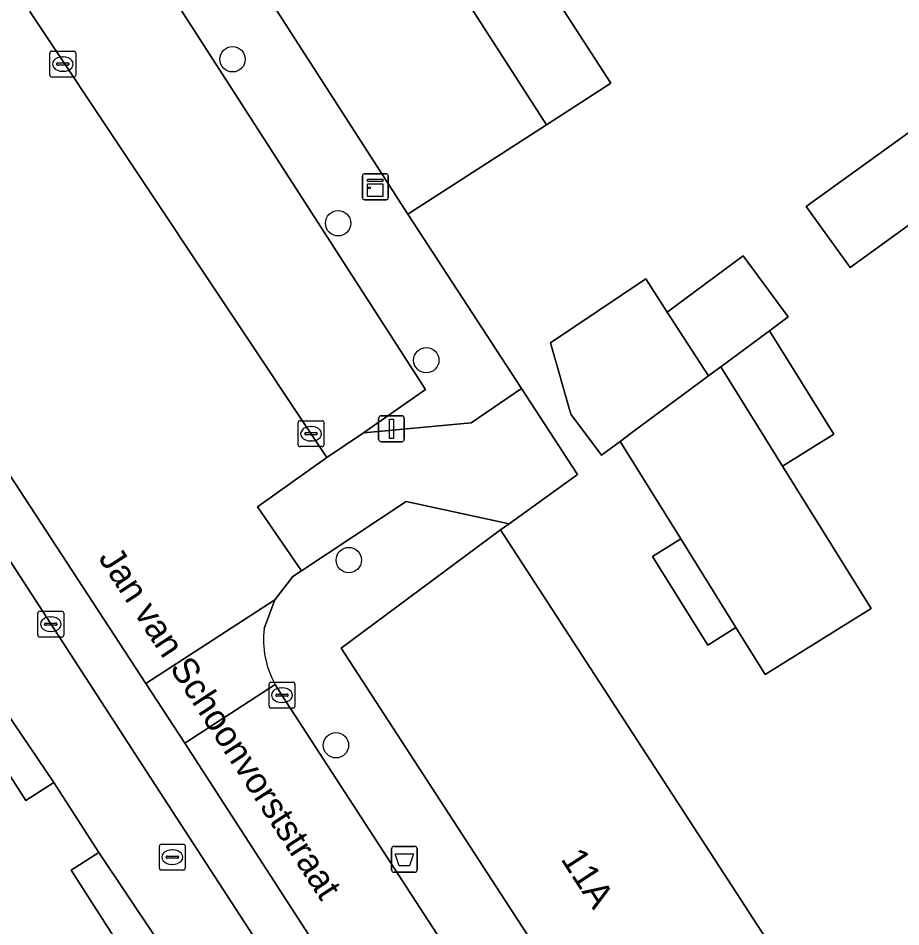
# Model space of a CAD drawing. Extents: x 161798 to 162385, y 382315 to 382833.
# Drawn here: x 161908.41 to 161942.5, y 382533.23 to 382568.31 of the extents above; entities that cross this region are included whole.
import ezdxf

# ---------------------------------------------------------------- set-up
doc = ezdxf.new("R2010")
doc.units = 0
for name, color, linetype in [('IMGEO_Afvalbak', 7, 'Continuous'), ('IMGEO_Boom', 7, 'Continuous'), ('IMGEO_Brandkraan', 7, 'Continuous'), ('IMGEO_Erf', 7, 'Continuous'), ('IMGEO_Kast', 7, 'Continuous'), ('IMGEO_Kolk', 7, 'Continuous'), ('IMGEO_Lichtmast', 7, 'Continuous'), ('IMGEO_Muur', 7, 'Continuous'), ('IMGEO_Openbare_ruimte_label', 7, 'Continuous'), ('IMGEO_Pand', 7, 'Continuous'), ('IMGEO_Pand_nummerreeks', 7, 'Continuous'), ('IMGEO_Parkeervlak_open', 7, 'Continuous'), ('IMGEO_Rijbaan_lokaal_open', 7, 'Continuous'), ('IMGEO_Voetpad_open', 7, 'Continuous')]:
    doc.layers.add(name, color=color, linetype=linetype)

msp = doc.modelspace()

# ---------------------------------------------------------------- linework, layer by layer
at = {"layer": 'IMGEO_Afvalbak'}
for p, q in [((161922.83, 382535.436), (161922.83, 382536.236)), ((161922.83, 382536.236), (161922.83, 382535.436)), ((161922.93, 382536.336), (161923.72, 382536.336)), ((161923.72, 382536.336), (161922.93, 382536.336)), ((161923.82, 382536.236), (161923.82, 382535.436)), ((161923.82, 382535.436), (161923.82, 382536.236)), ((161923.72, 382535.336), (161922.93, 382535.336)), ((161922.93, 382535.336), (161923.72, 382535.336))]:
    msp.add_line(p, q, dxfattribs=at)
msp.add_lwpolyline([(161922.973, 382536.05), (161923.677, 382536.05), (161923.528, 382535.58), (161923.122, 382535.58), (161922.973, 382536.05)], dxfattribs=at)
for centre, start, end in [((161922.93, 382536.236), 90, 180), ((161922.93, 382536.236), 90, 180), ((161923.72, 382536.236), 0, 90), ((161923.72, 382536.236), 360, 90), ((161922.93, 382535.436), 180, 270), ((161922.93, 382535.436), 180, 270), ((161923.72, 382535.436), 270, 0), ((161923.72, 382535.436), 270, 0)]:
    msp.add_arc(centre, 0.1, start, end, dxfattribs=at)
at = {"layer": 'IMGEO_Boom'}
for centre in [(161916.691, 382566.72), (161920.768, 382560.39), (161924.174, 382555.102), (161921.179, 382547.388), (161920.685, 382540.238)]:
    msp.add_circle(centre, 0.489, dxfattribs=at)
at = {"layer": 'IMGEO_Brandkraan'}
for p, q in [((161913.866, 382535.494), (161913.866, 382536.346)), ((161913.941, 382536.42), (161914.793, 382536.42)), ((161914.354, 382536.2), (161914.379, 382536.2)), ((161914.867, 382536.346), (161914.867, 382535.494)), ((161914.125, 382535.914), (161914.125, 382535.926)), ((161914.563, 382535.877), (161914.165, 382535.877)), ((161914.168, 382535.963), (161914.566, 382535.963)), ((161914.609, 382535.926), (161914.609, 382535.914)), ((161914.793, 382535.42), (161913.941, 382535.42)), ((161914.377, 382535.64), (161914.352, 382535.64))]:
    msp.add_line(p, q, dxfattribs=at)
for points in [[(161913.866, 382535.494), (161913.866, 382536.346)], [(161913.941, 382536.42), (161914.793, 382536.42)], [(161914.867, 382536.346), (161914.867, 382535.494)], [(161914.793, 382535.42), (161913.941, 382535.42)]]:
    msp.add_lwpolyline(points, dxfattribs=at)
for centre, radius, start, end in [((161913.943, 382536.344), 0.0765, 91.552, 178.448), ((161913.943, 382536.344), 0.0765, 91.552, 178.448), ((161914.791, 382536.344), 0.0765, 1.552, 88.448), ((161914.791, 382536.344), 0.0765, 1.552, 88.448), ((161914.165, 382535.923), 0.0403, 85.8775, 175.7526), ((161914.162, 382535.913), 0.0366, 178.938, 274.7102), ((161914.566, 382535.92), 0.043, 264.8664, 352.4533), ((161914.57, 382535.925), 0.0386, 1.7309, 96.639), ((161913.943, 382535.496), 0.0765, 181.552, 268.448), ((161913.943, 382535.496), 0.0765, 181.552, 268.448), ((161914.791, 382535.496), 0.0765, 271.552, 358.448), ((161914.791, 382535.496), 0.0765, 271.552, 358.448)]:
    msp.add_arc(centre, radius, start, end, dxfattribs=at)
for centre, major_axis, ratio, start_param, end_param in [((161914.353, 382535.92), (-0.387, 0.002), 0.722429, 4.712389, 7.853982), ((161914.378, 382535.92), (-0.39, 0.002), 0.717154, 1.570796, 4.712389)]:
    msp.add_ellipse(centre, major_axis=major_axis, ratio=ratio, start_param=start_param, end_param=end_param, dxfattribs=at)
at = {"layer": 'IMGEO_Erf'}
for points in [[(161945.057, 382574.729), (161940.162, 382571.576), (161937.799, 382570.027), (161937.504, 382569.837), (161935.277, 382573.295), (161932.843, 382571.727), (161929.049, 382569.284), (161931.298, 382565.792), (161928.82, 382564.196), (161923.464, 382560.747), (161927.849, 382554.013), (161930.015, 382550.687), (161927.378, 382548.793), (161927.045, 382548.554), (161941.278, 382526.66), (161942.03, 382525.503), (161945.338, 382527.569)], [(161889.755, 382530.763), (161886.621, 382535.643), (161887.378, 382536.128), (161899.179, 382543.71), (161903.381, 382546.409), (161908.71, 382538.113), (161909.788, 382538.805), (161900.489, 382552.547), (161897.075, 382557.59), (161893.716, 382555.371), (161890.552, 382560.159), (161883.925, 382555.781)], [(161924.608, 382516.565), (161911.526, 382536.099), (161910.458, 382535.413), (161915.897, 382526.946)]]:
    msp.add_lwpolyline(points, dxfattribs=at)
for points in [[(161945.946, 382562.594), (161940.543, 382558.688), (161938.848, 382561.033), (161944.377, 382565.031), (161949.608, 382568.813), (161951.303, 382566.468)], [(161941.353, 382545.523), (161937.26, 382542.972), (161936.132, 382544.781), (161935.046, 382544.104), (161932.91, 382547.532), (161933.996, 382548.209), (161931.654, 382551.965), (161930.934, 382551.433), (161929.755, 382553.026), (161928.969, 382555.771), (161932.652, 382558.246), (161933.478, 382556.963), (161936.408, 382559.133), (161938.152, 382556.779), (161937.423, 382556.239), (161939.908, 382552.253), (161937.928, 382551.018)]]:
    msp.add_lwpolyline(points, close=True, dxfattribs=at)
at = {"layer": 'IMGEO_Kast'}
for p, q in [((161921.706, 382561.372), (161921.706, 382562.213)), ((161921.706, 382562.213), (161921.706, 382561.372)), ((161921.781, 382562.297), (161922.622, 382562.297)), ((161922.622, 382562.297), (161921.781, 382562.297)), ((161922.706, 382562.222), (161922.706, 382561.381)), ((161922.706, 382561.381), (161922.706, 382562.222)), ((161922.631, 382561.297), (161921.79, 382561.297)), ((161921.79, 382561.297), (161922.631, 382561.297))]:
    msp.add_line(p, q, dxfattribs=at)
for points in [[(161921.901, 382562.087), (161922.501, 382562.087), (161922.501, 382562.002), (161921.901, 382562.002), (161921.901, 382562.087)], [(161921.901, 382561.912), (161922.501, 382561.912), (161922.501, 382561.423), (161921.901, 382561.423), (161921.901, 382561.912)]]:
    msp.add_lwpolyline(points, dxfattribs=at)
msp.add_circle((161921.985, 382561.761), 0.0377, dxfattribs=at)
for centre, start, end in [((161921.784, 382562.219), 92.4484, 184.2845), ((161921.784, 382562.219), 92.4484, 184.2845), ((161922.628, 382562.219), 2.4484, 94.2845), ((161922.628, 382562.219), 2.4484, 94.2845), ((161921.784, 382561.375), 182.4484, 274.2845), ((161921.784, 382561.375), 182.4484, 274.2845), ((161922.628, 382561.375), 272.4484, 4.2845), ((161922.628, 382561.375), 272.4484, 4.2845)]:
    msp.add_arc(centre, 0.0779, start, end, dxfattribs=at)
at = {"layer": 'IMGEO_Kolk'}
for p, q in [((161909.634, 382566.11), (161909.634, 382566.962)), ((161909.709, 382567.036), (161910.561, 382567.036)), ((161910.635, 382566.962), (161910.635, 382566.11)), ((161910.122, 382566.816), (161910.147, 382566.816)), ((161909.893, 382566.53), (161909.893, 382566.542)), ((161910.331, 382566.493), (161909.933, 382566.493)), ((161909.936, 382566.579), (161910.334, 382566.579)), ((161910.145, 382566.256), (161910.12, 382566.256)), ((161910.377, 382566.542), (161910.377, 382566.53)), ((161910.561, 382566.036), (161909.709, 382566.036)), ((161919.222, 382551.84), (161919.222, 382552.692)), ((161919.297, 382552.766), (161920.149, 382552.766)), ((161920.223, 382552.692), (161920.223, 382551.84)), ((161919.481, 382552.26), (161919.481, 382552.272)), ((161919.524, 382552.309), (161919.922, 382552.309)), ((161919.71, 382552.546), (161919.735, 382552.546)), ((161919.965, 382552.272), (161919.965, 382552.26)), ((161919.919, 382552.223), (161919.521, 382552.223)), ((161919.733, 382551.986), (161919.708, 382551.986)), ((161920.149, 382551.766), (161919.297, 382551.766)), ((161909.171, 382544.487), (161909.171, 382545.339)), ((161909.246, 382545.413), (161910.098, 382545.413)), ((161910.172, 382545.339), (161910.172, 382544.487)), ((161909.43, 382544.907), (161909.43, 382544.919)), ((161909.868, 382544.87), (161909.47, 382544.87)), ((161909.473, 382544.956), (161909.871, 382544.956)), ((161909.659, 382545.193), (161909.684, 382545.193)), ((161909.914, 382544.919), (161909.914, 382544.907)), ((161909.682, 382544.633), (161909.657, 382544.633)), ((161910.098, 382544.413), (161909.246, 382544.413)), ((161918.101, 382541.747), (161918.101, 382542.599)), ((161918.176, 382542.673), (161919.028, 382542.673)), ((161918.589, 382542.453), (161918.614, 382542.453)), ((161919.102, 382542.599), (161919.102, 382541.747)), ((161918.36, 382542.167), (161918.36, 382542.179)), ((161918.798, 382542.13), (161918.4, 382542.13)), ((161918.403, 382542.216), (161918.801, 382542.216)), ((161918.844, 382542.179), (161918.844, 382542.167)), ((161918.612, 382541.893), (161918.587, 382541.893)), ((161919.028, 382541.673), (161918.176, 382541.673))]:
    msp.add_line(p, q, dxfattribs=at)
for points in [[(161909.634, 382566.11), (161909.634, 382566.962)], [(161909.709, 382567.036), (161910.561, 382567.036)], [(161910.635, 382566.962), (161910.635, 382566.11)], [(161910.561, 382566.036), (161909.709, 382566.036)], [(161919.222, 382551.84), (161919.222, 382552.692)], [(161919.297, 382552.766), (161920.149, 382552.766)], [(161920.223, 382552.692), (161920.223, 382551.84)], [(161920.149, 382551.766), (161919.297, 382551.766)], [(161909.171, 382544.487), (161909.171, 382545.339)], [(161909.246, 382545.413), (161910.098, 382545.413)], [(161910.172, 382545.339), (161910.172, 382544.487)], [(161910.098, 382544.413), (161909.246, 382544.413)], [(161918.101, 382541.747), (161918.101, 382542.599)], [(161918.176, 382542.673), (161919.028, 382542.673)], [(161919.102, 382542.599), (161919.102, 382541.747)], [(161919.028, 382541.673), (161918.176, 382541.673)]]:
    msp.add_lwpolyline(points, dxfattribs=at)
for centre, radius, start, end in [((161909.711, 382566.96), 0.0765, 91.552, 178.448), ((161909.711, 382566.96), 0.0765, 91.552, 178.448), ((161910.559, 382566.96), 0.0765, 1.552, 88.448), ((161910.559, 382566.96), 0.0765, 1.552, 88.448), ((161909.933, 382566.539), 0.0403, 85.8775, 175.7526), ((161909.93, 382566.529), 0.0366, 178.938, 274.7102), ((161910.334, 382566.536), 0.043, 264.8664, 352.4533), ((161910.338, 382566.541), 0.0386, 1.7309, 96.639), ((161909.711, 382566.112), 0.0765, 181.552, 268.448), ((161909.711, 382566.112), 0.0765, 181.552, 268.448), ((161910.559, 382566.112), 0.0765, 271.552, 358.448), ((161910.559, 382566.112), 0.0765, 271.552, 358.448), ((161919.299, 382552.69), 0.0765, 91.552, 178.448), ((161919.299, 382552.69), 0.0765, 91.552, 178.448), ((161920.147, 382552.69), 0.0765, 1.552, 88.448), ((161920.147, 382552.69), 0.0765, 1.552, 88.448), ((161919.521, 382552.269), 0.0403, 85.8775, 175.7526), ((161919.518, 382552.259), 0.0366, 178.938, 274.7102), ((161919.922, 382552.266), 0.043, 264.8664, 352.4533), ((161919.926, 382552.271), 0.0386, 1.7309, 96.639), ((161919.299, 382551.842), 0.0765, 181.552, 268.448), ((161919.299, 382551.842), 0.0765, 181.552, 268.448), ((161920.147, 382551.842), 0.0765, 271.552, 358.448), ((161920.147, 382551.842), 0.0765, 271.552, 358.448), ((161909.248, 382545.337), 0.0765, 91.552, 178.448), ((161909.248, 382545.337), 0.0765, 91.552, 178.448), ((161910.096, 382545.337), 0.0765, 1.552, 88.448), ((161910.096, 382545.337), 0.0765, 1.552, 88.448), ((161909.47, 382544.916), 0.0403, 85.8775, 175.7526), ((161909.467, 382544.906), 0.0366, 178.938, 274.7102), ((161909.871, 382544.913), 0.043, 264.8664, 352.4533), ((161909.875, 382544.918), 0.0386, 1.7309, 96.639), ((161909.248, 382544.489), 0.0765, 181.552, 268.448), ((161909.248, 382544.489), 0.0765, 181.552, 268.448), ((161910.096, 382544.489), 0.0765, 271.552, 358.448), ((161910.096, 382544.489), 0.0765, 271.552, 358.448), ((161918.178, 382542.597), 0.0765, 91.552, 178.448), ((161918.178, 382542.597), 0.0765, 91.552, 178.448), ((161919.026, 382542.597), 0.0765, 1.552, 88.448), ((161919.026, 382542.597), 0.0765, 1.552, 88.448), ((161918.4, 382542.176), 0.0403, 85.8775, 175.7526), ((161918.397, 382542.166), 0.0366, 178.938, 274.7102), ((161918.801, 382542.173), 0.043, 264.8664, 352.4533), ((161918.805, 382542.178), 0.0386, 1.7309, 96.639), ((161918.178, 382541.749), 0.0765, 181.552, 268.448), ((161918.178, 382541.749), 0.0765, 181.552, 268.448), ((161919.026, 382541.749), 0.0765, 271.552, 358.448), ((161919.026, 382541.749), 0.0765, 271.552, 358.448)]:
    msp.add_arc(centre, radius, start, end, dxfattribs=at)
for centre, major_axis, ratio, start_param, end_param in [((161910.121, 382566.536), (-0.387, 0.002), 0.722429, 4.712389, 7.853982), ((161910.146, 382566.536), (-0.39, 0.002), 0.717154, 1.570796, 4.712389), ((161919.709, 382552.266), (-0.387, 0.002), 0.722429, 4.712389, 7.853982), ((161919.734, 382552.266), (-0.39, 0.002), 0.717154, 1.570796, 4.712389), ((161909.658, 382544.913), (-0.387, 0.002), 0.722429, 4.712389, 7.853982), ((161909.683, 382544.913), (-0.39, 0.002), 0.717154, 1.570796, 4.712389), ((161918.588, 382542.173), (-0.387, 0.002), 0.722429, 4.712389, 7.853982), ((161918.613, 382542.173), (-0.39, 0.002), 0.717154, 1.570796, 4.712389)]:
    msp.add_ellipse(centre, major_axis=major_axis, ratio=ratio, start_param=start_param, end_param=end_param, dxfattribs=at)
at = {"layer": 'IMGEO_Lichtmast'}
for p, q in [((161922.433, 382552.958), (161923.223, 382552.958)), ((161923.223, 382552.958), (161922.433, 382552.958)), ((161922.333, 382552.058), (161922.333, 382552.858)), ((161922.333, 382552.858), (161922.333, 382552.058)), ((161923.323, 382552.858), (161923.323, 382552.058)), ((161923.323, 382552.058), (161923.323, 382552.858)), ((161923.223, 382551.958), (161922.433, 382551.958)), ((161922.433, 382551.958), (161923.223, 382551.958))]:
    msp.add_line(p, q, dxfattribs=at)
msp.add_lwpolyline([(161922.753, 382552.833), (161922.903, 382552.833), (161922.903, 382552.083), (161922.753, 382552.083), (161922.753, 382552.833)], dxfattribs=at)
for centre, start, end in [((161922.433, 382552.858), 90, 180), ((161922.433, 382552.858), 90, 180), ((161923.223, 382552.858), 0, 90), ((161923.223, 382552.858), 360, 90), ((161922.433, 382552.058), 180, 270), ((161922.433, 382552.058), 180, 270), ((161923.223, 382552.058), 270, 0), ((161923.223, 382552.058), 270, 0)]:
    msp.add_arc(centre, 0.1, start, end, dxfattribs=at)
at = {"layer": 'IMGEO_Muur'}
for points in [[(161923.464, 382560.747), (161927.849, 382554.013)], [(161927.849, 382554.013), (161930.015, 382550.687)]]:
    msp.add_lwpolyline(points, dxfattribs=at)
at = {"layer": 'IMGEO_Pand'}
for points in [[(161928.82, 382564.196), (161931.298, 382565.792), (161929.049, 382569.284), (161932.843, 382571.727), (161928.086, 382579.115), (161921.815, 382575.076)], [(161928.82, 382564.196), (161921.815, 382575.076), (161916.457, 382571.625), (161923.464, 382560.747)], [(161945.946, 382562.594), (161944.377, 382565.031), (161938.848, 382561.033), (161940.543, 382558.688)], [(161938.152, 382556.779), (161936.408, 382559.133), (161933.478, 382556.963), (161935.067, 382554.495), (161935.223, 382554.61), (161935.542, 382554.846), (161937.423, 382556.239)], [(161933.478, 382556.963), (161932.652, 382558.246), (161928.969, 382555.771), (161929.755, 382553.026), (161930.934, 382551.433), (161931.654, 382551.965), (161932.099, 382552.296), (161935.067, 382554.495)], [(161937.423, 382556.239), (161935.542, 382554.846), (161937.928, 382551.018), (161939.908, 382552.253)], [(161937.928, 382551.018), (161935.542, 382554.846), (161935.223, 382554.61), (161935.067, 382554.495), (161932.099, 382552.296), (161931.654, 382551.965), (161933.996, 382548.209), (161936.132, 382544.781), (161937.26, 382542.972), (161941.353, 382545.523)], [(161927.045, 382548.554), (161920.885, 382543.991), (161934.863, 382522.49), (161936.739, 382519.665), (161939.538, 382521.355), (161943.233, 382523.653), (161942.03, 382525.503), (161941.278, 382526.66)], [(161933.996, 382548.209), (161932.91, 382547.532), (161935.046, 382544.104), (161936.132, 382544.781)], [(161911.526, 382536.099), (161909.788, 382538.805), (161908.71, 382538.113), (161903.381, 382546.409), (161899.179, 382543.71), (161887.378, 382536.128), (161886.621, 382535.643), (161889.755, 382530.763), (161887.039, 382529.019), (161888.906, 382526.293), (161891.059, 382523.15), (161891.795, 382522.077), (161896.844, 382514.707), (161899.137, 382516.18), (161899.885, 382516.66), (161911.691, 382524.244), (161915.897, 382526.946), (161910.458, 382535.413)]]:
    msp.add_lwpolyline(points, close=True, dxfattribs=at)
at = {"layer": 'IMGEO_Parkeervlak_open'}
for points in [[(161912.156, 382570.649), (161908.867, 382568.56), (161920.339, 382551.345), (161921.747, 382552.303), (161924.147, 382553.977), (161913.616, 382570.328)], [(161901.148, 382565.237), (161899.405, 382564.11), (161897.868, 382563.115), (161900.583, 382558.931), (161913.397, 382539.189), (161920.246, 382528.65), (161922.307, 382525.478), (161922.992, 382524.425), (161930.297, 382513.067), (161934.984, 382505.994), (161936.464, 382506.883), (161932.801, 382512.548), (161914.845, 382540.321), (161913.348, 382542.627), (161904.811, 382555.675), (161902.142, 382559.943), (161904.859, 382561.676), (161902.151, 382565.965), (161901.379, 382565.494)]]:
    msp.add_lwpolyline(points, dxfattribs=at)
at = {"layer": 'IMGEO_Rijbaan_lokaal_open'}
for points in [[(161901.379, 382565.494), (161902.151, 382565.965), (161904.859, 382561.676), (161902.142, 382559.943), (161904.811, 382555.675), (161913.348, 382542.627), (161918.319, 382545.854), (161919.014, 382546.754), (161919.354, 382546.979), (161917.654, 382549.445), (161920.339, 382551.345), (161908.867, 382568.56)], [(161917.915, 382544.747), (161918.319, 382545.854), (161913.348, 382542.627), (161914.845, 382540.321), (161918.335, 382542.587)]]:
    msp.add_lwpolyline(points, dxfattribs=at)
msp.add_lwpolyline([(161914.845, 382540.321), (161932.801, 382512.548), (161936.334, 382514.781), (161934.769, 382517.192), (161934.683, 382517.328), (161932.663, 382520.514), (161918.599, 382542.176), (161918.335, 382542.587)], close=True, dxfattribs=at)
msp.add_arc((161921.471, 382544.318), 3.582, 173.1139, 208.8932, dxfattribs=at)
at = {"layer": 'IMGEO_Voetpad_open'}
for points in [[(161902.451, 382574.778), (161900.916, 382577.172), (161899.894, 382578.767), (161898.121, 382577.665), (161900.68, 382573.632), (161892.965, 382568.536), (161890.792, 382567.1), (161891.64, 382565.816), (161892.451, 382564.589), (161893.911, 382562.378), (161897.075, 382557.59), (161900.489, 382552.547), (161909.788, 382538.805), (161911.526, 382536.099), (161924.608, 382516.565), (161924.902, 382516.697), (161927.077, 382513.05), (161929.9, 382508.429), (161930.116, 382508.56), (161934.536, 382501.323), (161934.577, 382498.82)], [(161913.616, 382570.328), (161924.147, 382553.977), (161921.747, 382552.303), (161925.907, 382552.689), (161927.849, 382554.013), (161923.464, 382560.747), (161916.457, 382571.625), (161913.539, 382574.028)], [(161930.297, 382513.067), (161922.992, 382524.425), (161922.307, 382525.478), (161921.886, 382525.209), (161919.846, 382528.394), (161920.246, 382528.65), (161913.397, 382539.189), (161900.583, 382558.931), (161897.868, 382563.115), (161899.405, 382564.11), (161901.148, 382565.237)], [(161936.739, 382519.665), (161934.863, 382522.49), (161920.885, 382543.991), (161927.045, 382548.554), (161927.378, 382548.793), (161923.398, 382549.654), (161919.354, 382546.979), (161919.014, 382546.754), (161918.319, 382545.854), (161917.915, 382544.747)], [(161918.335, 382542.587), (161918.599, 382542.176), (161932.663, 382520.514), (161933.081, 382520.788), (161935.149, 382517.634), (161934.683, 382517.328), (161934.769, 382517.192), (161936.334, 382514.781), (161940.936, 382507.628)]]:
    msp.add_lwpolyline(points, dxfattribs=at)
msp.add_lwpolyline([(161919.354, 382546.979), (161923.398, 382549.654), (161927.378, 382548.793), (161930.015, 382550.687), (161927.849, 382554.013), (161925.907, 382552.689), (161921.747, 382552.303), (161920.339, 382551.345), (161917.654, 382549.445)], close=True, dxfattribs=at)
msp.add_arc((161921.471, 382544.318), 3.582, 173.1139, 208.8932, dxfattribs=at)

# ---------------------------------------------------------------- texts
at = {"layer": 'IMGEO_Openbare_ruimte_label'}
msp.add_text('Jan van Schoonvorststraat', height=1, rotation=303.0383, dxfattribs=at).set_placement((161911.486, 382547.467))
at = {"layer": 'IMGEO_Pand_nummerreeks'}
msp.add_text('11A', height=1, rotation=302.9277, dxfattribs=at).set_placement((161929.344, 382535.848))

doc.saveas('drawing.dxf')
